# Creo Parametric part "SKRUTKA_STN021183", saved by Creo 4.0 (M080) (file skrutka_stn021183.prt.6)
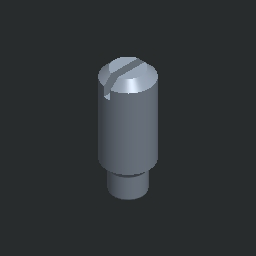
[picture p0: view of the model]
Units: Custom; MM, KILOGRAM, SECS
Materials in the file: OCEL, OCEL_N

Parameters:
  PTC_MATERIAL_NAME = "OCEL"
  NAZOV = "SKRUTKA_STN021183"
  NORMA = "STN 02 1183"

Other parameters: HMOTNOST, HUSTOTA, D11

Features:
  1. round
  2. round
  3. chamfer
  4. datum plane "DTM2"
  5. datum plane "DTM4"
  6. datum plane "DTM5"

Other named items: THRU

Layers: 1, 2, 3, 4, 5, 6, 7, 8, 9, 10, 11, 12, 13, 14, 15, 16, 17, 18, 19, 20, 21, 22, 23, 24, 25, 26, 27, 28, 29, 30, 31, 32

Family table entries: GENERIC, SKRUTKA_M2, SKRUTKA_STN021183, value(d_val), value(i_val), SKRUTKA_M2_5, SKRUTKA_STN021183, SKRUTKA_M3, SKRUTKA_STN021183, SKRUTKA_M3_5, SKRUTKA_STN021183, SKRUTKA_M4, SKRUTKA_STN021183, SKRUTKA_M5, SKRUTKA_STN021183, SKRUTKA_M6, SKRUTKA_STN021183, SKRUTKA_M8, SKRUTKA_STN021183, !/ , SKRUTKA_M10, SKRUTKA_STN021183, !/$, SKRUTKA_M12, SKRUTKA_STN021183, !/(, 2/!, SKRUTKA_M16, SKRUTKA_STN021183, !/0, 2/(, 2/ , # Pro/TABLE, [] S 92;, [] W 10;, [A] W  3;, [B] W 13;, [C] W 10;, [D] W 10;, [E] W 10;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

Surfaces: 7 plane, 6 cylinder, 4 torus, 3 cone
